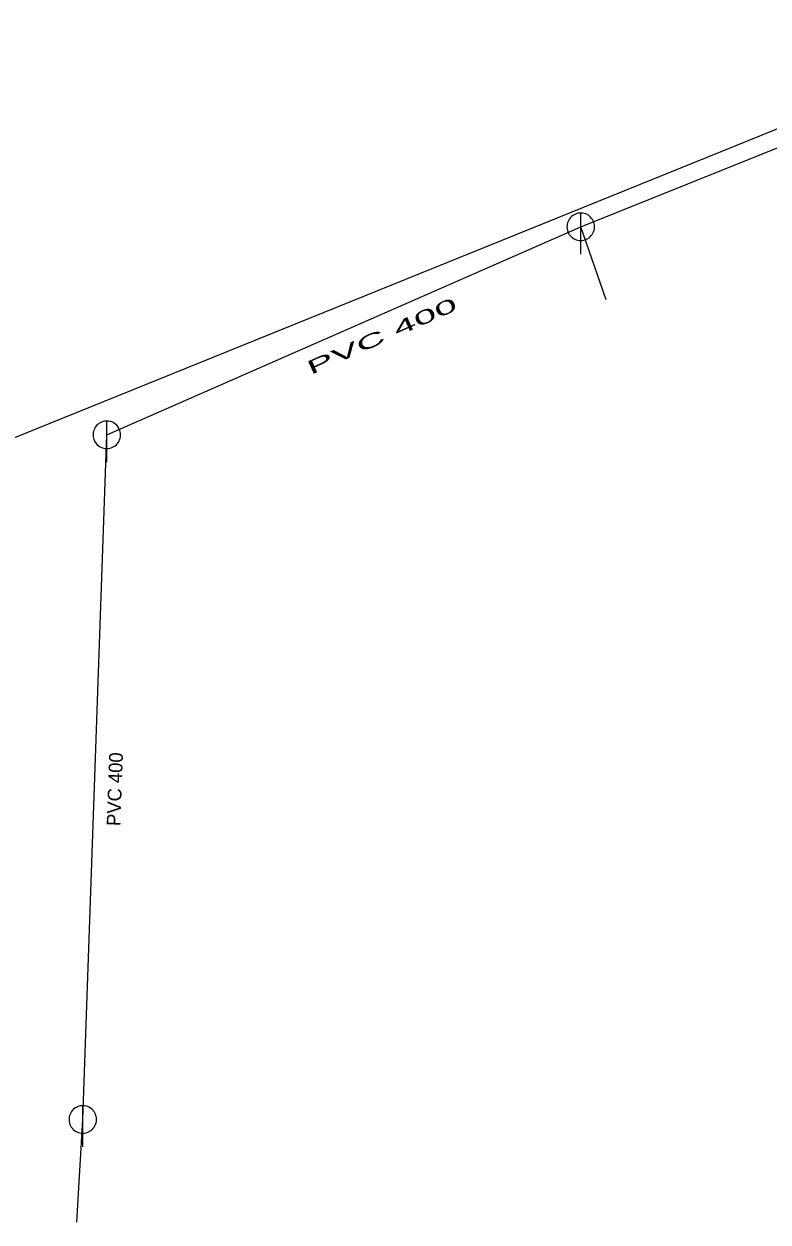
# Model space of a CAD drawing. Extents: x -783064 to -782702, y -1007904 to -1007145.
# Drawn here: x -782909 to -782854.9, y -1007904 to -1007817 of the extents above; entities that cross this region are included whole.
import ezdxf

# ---------------------------------------------------------------- set-up
doc = ezdxf.new("R2010")
doc.units = 0
doc.header["$LTSCALE"] = 0.4
for name, color, linetype, lineweight in [('1', 7, 'Continuous', 13), ('11', 7, 'Continuous', 13), ('14', 7, 'Continuous', 13), ('17', 7, 'Continuous', 25), ('22', 7, 'Continuous', 13)]:
    doc.layers.add(name, color=color, linetype=linetype, lineweight=lineweight)

msp = doc.modelspace()

# ---------------------------------------------------------------- linework, layer by layer
at = {"layer": '11'}
msp.add_line((-782866.654, -1007837.027), (-782868.51, -1007831.71), dxfattribs=at)
at = {"layer": '14', "lineweight": 25}
for p, q in [((-782868.51, -1007831.71), (-782833.46, -1007817.64)), ((-782902.96, -1007846.83), (-782868.51, -1007831.71)), ((-782904.71, -1007896.59), (-782902.96, -1007846.83)), ((-782905.143, -1007904.044), (-782904.71, -1007896.59))]:
    msp.add_line(p, q, dxfattribs=at)
at = {"layer": '17'}
msp.add_lwpolyline([(-783063.843, -1007879.786), (-783019.96, -1007877.952), (-783013.339, -1007877.559), (-782960.98, -1007867.795), (-782835.384, -1007816.97)], dxfattribs=at)
at = {"layer": '22'}
for p, q in [((-782868.51, -1007833.71), (-782868.509, -1007830.71)), ((-782902.96, -1007848.83), (-782902.959, -1007845.83)), ((-782904.71, -1007898.59), (-782904.709, -1007895.59))]:
    msp.add_line(p, q, dxfattribs=at)
for points in [[(-782867.51, -1007831.71), (-782867.515, -1007831.601), (-782867.533, -1007831.493), (-782867.563, -1007831.387), (-782867.603, -1007831.286), (-782867.655, -1007831.189), (-782867.717, -1007831.099), (-782867.789, -1007831.016), (-782867.869, -1007830.942), (-782867.957, -1007830.876), (-782868.051, -1007830.821), (-782868.151, -1007830.776), (-782868.256, -1007830.743), (-782868.363, -1007830.721), (-782868.472, -1007830.711), (-782868.582, -1007830.713), (-782868.69, -1007830.727), (-782868.797, -1007830.752), (-782868.9, -1007830.789), (-782868.998, -1007830.838), (-782869.09, -1007830.896), (-782869.176, -1007830.965), (-782869.253, -1007831.042), (-782869.322, -1007831.128), (-782869.381, -1007831.22), (-782869.429, -1007831.318), (-782869.466, -1007831.421), (-782869.492, -1007831.528), (-782869.506, -1007831.636), (-782869.509, -1007831.746), (-782869.499, -1007831.855), (-782869.478, -1007831.962), (-782869.444, -1007832.066), (-782869.4, -1007832.166), (-782869.345, -1007832.261), (-782869.279, -1007832.349), (-782869.205, -1007832.429), (-782869.122, -1007832.501), (-782869.032, -1007832.563), (-782868.936, -1007832.615), (-782868.834, -1007832.656), (-782868.729, -1007832.686), (-782868.621, -1007832.704), (-782868.511, -1007832.71), (-782868.402, -1007832.704), (-782868.294, -1007832.686), (-782868.189, -1007832.657), (-782868.087, -1007832.616), (-782867.99, -1007832.564), (-782867.9, -1007832.502), (-782867.817, -1007832.431), (-782867.742, -1007832.351), (-782867.677, -1007832.263), (-782867.621, -1007832.169), (-782867.577, -1007832.069), (-782867.543, -1007831.965), (-782867.521, -1007831.857), (-782867.511, -1007831.748)], [(-782901.96, -1007846.83), (-782901.965, -1007846.721), (-782901.983, -1007846.613), (-782902.013, -1007846.507), (-782902.053, -1007846.406), (-782902.105, -1007846.309), (-782902.167, -1007846.219), (-782902.239, -1007846.136), (-782902.319, -1007846.062), (-782902.407, -1007845.996), (-782902.501, -1007845.941), (-782902.601, -1007845.896), (-782902.706, -1007845.863), (-782902.813, -1007845.841), (-782902.922, -1007845.831), (-782903.032, -1007845.833), (-782903.14, -1007845.847), (-782903.247, -1007845.872), (-782903.35, -1007845.909), (-782903.448, -1007845.958), (-782903.54, -1007846.016), (-782903.626, -1007846.085), (-782903.703, -1007846.162), (-782903.772, -1007846.248), (-782903.831, -1007846.34), (-782903.879, -1007846.438), (-782903.916, -1007846.541), (-782903.942, -1007846.648), (-782903.956, -1007846.756), (-782903.959, -1007846.866), (-782903.949, -1007846.975), (-782903.928, -1007847.082), (-782903.894, -1007847.186), (-782903.85, -1007847.286), (-782903.795, -1007847.381), (-782903.729, -1007847.469), (-782903.655, -1007847.549), (-782903.572, -1007847.621), (-782903.482, -1007847.683), (-782903.386, -1007847.735), (-782903.284, -1007847.776), (-782903.179, -1007847.806), (-782903.071, -1007847.824), (-782902.961, -1007847.83), (-782902.852, -1007847.824), (-782902.744, -1007847.806), (-782902.639, -1007847.777), (-782902.537, -1007847.736), (-782902.44, -1007847.684), (-782902.35, -1007847.622), (-782902.267, -1007847.551), (-782902.192, -1007847.471), (-782902.127, -1007847.383), (-782902.071, -1007847.289), (-782902.027, -1007847.189), (-782901.993, -1007847.085), (-782901.971, -1007846.977), (-782901.961, -1007846.868)], [(-782903.71, -1007896.59), (-782903.715, -1007896.481), (-782903.733, -1007896.373), (-782903.763, -1007896.267), (-782903.803, -1007896.166), (-782903.855, -1007896.069), (-782903.917, -1007895.979), (-782903.989, -1007895.896), (-782904.069, -1007895.822), (-782904.157, -1007895.756), (-782904.251, -1007895.701), (-782904.351, -1007895.656), (-782904.456, -1007895.623), (-782904.563, -1007895.601), (-782904.672, -1007895.591), (-782904.782, -1007895.593), (-782904.89, -1007895.607), (-782904.997, -1007895.632), (-782905.1, -1007895.669), (-782905.198, -1007895.718), (-782905.29, -1007895.776), (-782905.376, -1007895.845), (-782905.453, -1007895.922), (-782905.522, -1007896.008), (-782905.581, -1007896.1), (-782905.629, -1007896.198), (-782905.666, -1007896.301), (-782905.692, -1007896.408), (-782905.706, -1007896.516), (-782905.709, -1007896.626), (-782905.699, -1007896.735), (-782905.678, -1007896.842), (-782905.644, -1007896.946), (-782905.6, -1007897.046), (-782905.545, -1007897.141), (-782905.479, -1007897.229), (-782905.405, -1007897.309), (-782905.322, -1007897.381), (-782905.232, -1007897.443), (-782905.136, -1007897.495), (-782905.034, -1007897.536), (-782904.929, -1007897.566), (-782904.821, -1007897.584), (-782904.711, -1007897.59), (-782904.602, -1007897.584), (-782904.494, -1007897.566), (-782904.389, -1007897.537), (-782904.287, -1007897.496), (-782904.19, -1007897.444), (-782904.1, -1007897.382), (-782904.017, -1007897.311), (-782903.942, -1007897.231), (-782903.877, -1007897.143), (-782903.821, -1007897.049), (-782903.777, -1007896.949), (-782903.743, -1007896.845), (-782903.721, -1007896.737), (-782903.711, -1007896.628)]]:
    msp.add_lwpolyline(points, close=True, dxfattribs=at)

# ---------------------------------------------------------------- texts
at = {"layer": '1', "width": 2.2}
msp.add_text('PVC 400 ', height=1, rotation=24, dxfattribs=at).set_placement((-782888.141, -1007842.494))
at = {"layer": '1'}
msp.add_text('PVC 400 ', height=1, rotation=88, dxfattribs=at).set_placement((-782901.973, -1007875.277))

doc.saveas('drawing.dxf')
